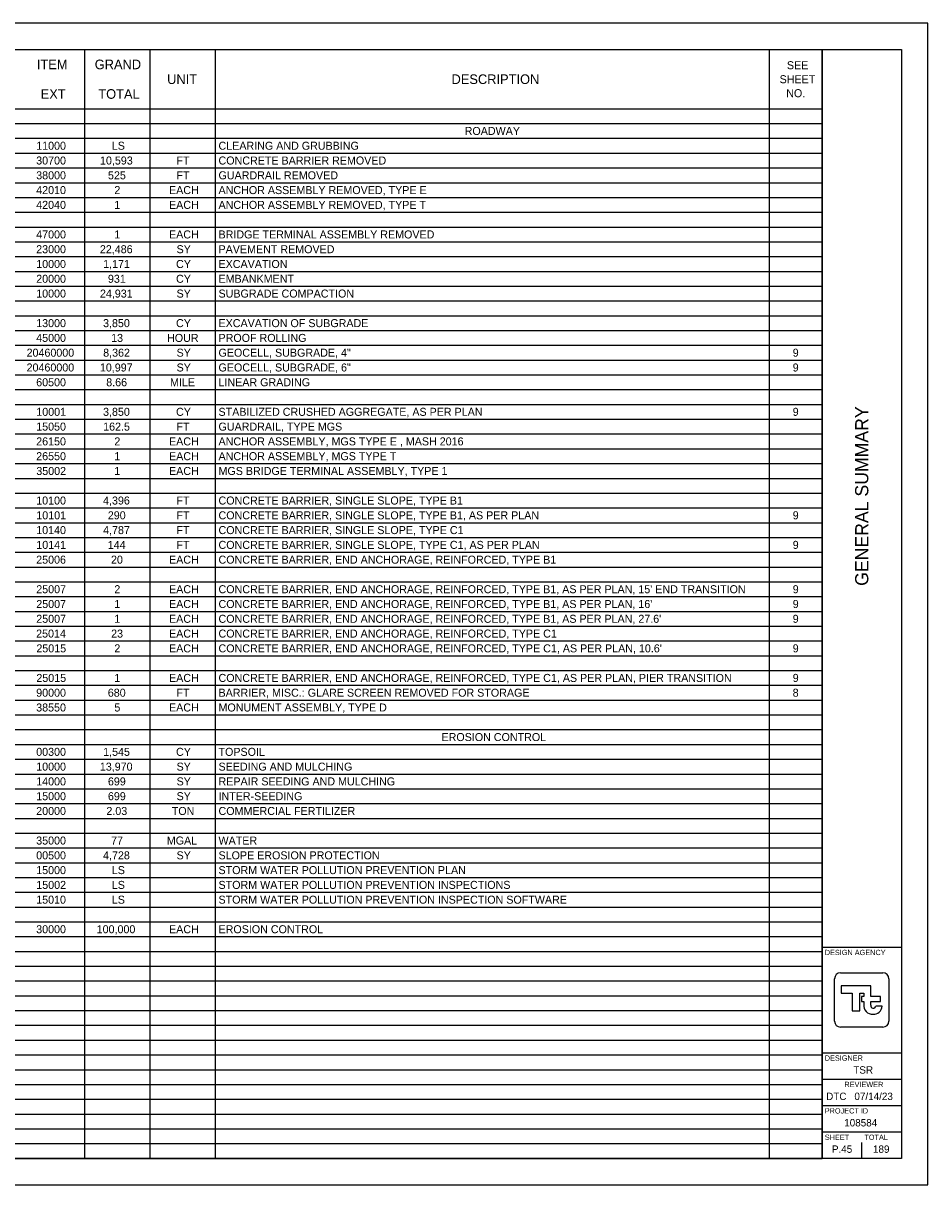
# Model space of a CAD drawing. Extents: x 0 to 34, y 0 to 22.
# Drawn here: x 16.87 to 34, y 0 to 22 of the extents above; entities that cross this region are included whole.
import ezdxf

# ---------------------------------------------------------------- set-up
doc = ezdxf.new("R2010")
doc.units = 0
for name, color, linetype in [('Default', 7, 'Continuous'), ('SH_Border', 7, 'Continuous'), ('SH_Cut_Line', 7, 'Continuous'), ('SH_Data', 7, 'Continuous')]:
    doc.layers.add(name, color=color, linetype=linetype)

msp = doc.modelspace()

# ---------------------------------------------------------------- linework, layer by layer
at = {"layer": 'Default'}
for p, q in [((1.5, 21.5), (32, 21.5)), ((18.035, 21.5), (18.035, 0.5)), ((19.27, 21.5), (19.27, 0.5)), ((20.505, 21.5), (20.505, 0.5)), ((30.995, 21.5), (30.995, 0.5)), ((32, 21.5), (32, 0.5)), ((1.5, 20.38), (32, 20.38)), ((1.5, 20.1), (32, 20.1)), ((1.5, 19.82), (32, 19.82)), ((1.5, 19.54), (32, 19.54)), ((1.5, 19.26), (32, 19.26)), ((1.5, 18.98), (32, 18.98)), ((1.5, 18.7), (32, 18.7)), ((1.5, 18.42), (32, 18.42)), ((1.5, 18.14), (32, 18.14)), ((1.5, 17.86), (32, 17.86)), ((1.5, 17.58), (32, 17.58)), ((1.5, 17.3), (32, 17.3)), ((1.5, 17.02), (32, 17.02)), ((1.5, 16.74), (32, 16.74)), ((1.5, 16.46), (32, 16.46)), ((1.5, 16.18), (32, 16.18)), ((1.5, 15.9), (32, 15.9)), ((1.5, 15.62), (32, 15.62)), ((1.5, 15.34), (32, 15.34)), ((1.5, 15.06), (32, 15.06)), ((1.5, 14.78), (32, 14.78)), ((1.5, 14.5), (32, 14.5)), ((1.5, 14.22), (32, 14.22)), ((1.5, 13.94), (32, 13.94)), ((1.5, 13.66), (32, 13.66)), ((1.5, 13.38), (32, 13.38)), ((1.5, 13.1), (32, 13.1)), ((1.5, 12.82), (32, 12.82)), ((1.5, 12.54), (32, 12.54)), ((1.5, 12.26), (32, 12.26)), ((1.5, 11.98), (32, 11.98)), ((1.5, 11.7), (32, 11.7)), ((1.5, 11.42), (32, 11.42)), ((1.5, 11.14), (32, 11.14)), ((1.5, 10.86), (32, 10.86)), ((1.5, 10.58), (32, 10.58)), ((1.5, 10.3), (32, 10.3)), ((1.5, 10.02), (32, 10.02)), ((1.5, 9.74), (32, 9.74)), ((1.5, 9.46), (32, 9.46)), ((1.5, 9.18), (32, 9.18)), ((1.5, 8.9), (32, 8.9)), ((1.5, 8.62), (32, 8.62)), ((1.5, 8.34), (32, 8.34)), ((1.5, 8.06), (32, 8.06)), ((1.5, 7.78), (32, 7.78)), ((1.5, 7.5), (32, 7.5)), ((1.5, 7.22), (32, 7.22)), ((1.5, 6.94), (32, 6.94)), ((1.5, 6.66), (32, 6.66)), ((1.5, 6.38), (32, 6.38)), ((1.5, 6.1), (32, 6.1)), ((1.5, 5.82), (32, 5.82)), ((1.5, 5.54), (32, 5.54)), ((1.5, 5.26), (32, 5.26)), ((1.5, 4.98), (32, 4.98)), ((1.5, 4.7), (32, 4.7)), ((1.5, 4.42), (32, 4.42)), ((1.5, 4.14), (32, 4.14)), ((1.5, 3.86), (32, 3.86)), ((1.5, 3.58), (32, 3.58)), ((1.5, 3.3), (32, 3.3)), ((1.5, 3.02), (32, 3.02)), ((1.5, 2.74), (32, 2.74)), ((1.5, 2.46), (32, 2.46)), ((1.5, 2.18), (32, 2.18)), ((1.5, 1.9), (32, 1.9)), ((1.5, 1.62), (32, 1.62)), ((1.5, 1.34), (32, 1.34)), ((1.5, 1.06), (32, 1.06)), ((1.5, 0.78), (32, 0.78)), ((1.5, 0.5), (32, 0.5))]:
    msp.add_line(p, q, dxfattribs=at)
at = {"layer": 'SH_Border'}
for p, q in [((32, 0.5), (32, 21.5)), ((32, 4.5), (33.5, 4.5)), ((32, 2.5), (33.5, 2.5)), ((32, 2), (33.5, 2)), ((32, 1.5), (33.5, 1.5)), ((32, 1), (33.5, 1))]:
    msp.add_line(p, q, dxfattribs=at)
msp.add_lwpolyline([(1.5, 21.5), (33.5, 21.5), (33.5, 0.5), (1.5, 0.5)], close=True, dxfattribs=at)
at = {"layer": 'SH_Cut_Line'}
msp.add_lwpolyline([(0, 0), (34, 0), (34, 22), (0, 22)], close=True, dxfattribs=at)
at = {"layer": 'SH_Data'}
for p, q in [((32.75, 3.5), (32.75, 3.5)), ((32.791, 3.415), (32.791, 3.415)), ((33.136, 3.385), (33.015, 3.385)), ((32.375, 0.675), (32.375, 0.675)), ((32.75, 0.5), (32.75, 0.8))]:
    msp.add_line(p, q, dxfattribs=at)
for points in [[(32.348, 4.014), (33.152, 4.014)], [(32.236, 3.099), (32.236, 3.901)], [(32.922, 3.399), (32.922, 3.47), (33.107, 3.47), (33.107, 3.568), (32.922, 3.568), (32.922, 3.768), (32.361, 3.768), (32.361, 3.632), (32.566, 3.632), (32.566, 3.294), (32.715, 3.294), (32.715, 3.63), (32.79, 3.63), (32.79, 3.568), (32.748, 3.568), (32.748, 3.47), (32.79, 3.47), (32.79, 3.415), (32.791, 3.415)], [(33.264, 3.901), (33.264, 3.099)], [(33.152, 2.986), (32.348, 2.986)]]:
    msp.add_lwpolyline(points, dxfattribs=at)
for centre, radius, start, end in [((32.348, 3.901), 0.113, 90, 180), ((33.152, 3.901), 0.113, 360, 90), ((32.949, 3.392), 0.16, 171.8856, 274.8323), ((32.968, 3.392), 0.0473, 171.8856, 350.9243), ((32.976, 3.392), 0.16, 265.1677, 357.3201), ((32.348, 3.099), 0.113, 180, 270), ((33.152, 3.099), 0.113, 270, 360)]:
    msp.add_arc(centre, radius, start, end, dxfattribs=at)

# ---------------------------------------------------------------- texts
at = {"layer": 'Default'}
for s, height, p in [('ITEM', 0.1818, (17.131, 21.129)), ('GRAND', 0.1818, (18.227, 21.129)), ('SEE ', 0.1515, (31.333, 21.129)), ('UNIT', 0.1818, (19.598, 20.849)), ('DESCRIPTION', 0.18184, (24.983, 20.849)), ('SHEET ', 0.1515, (31.195, 20.864)), ('EXT', 0.1818, (17.204, 20.569)), ('TOTAL', 0.1818, (18.295, 20.569)), ('NO.', 0.1515, (31.32, 20.599)), ('ROADWAY', 0.1515, (25.232, 19.884)), ('11000', 0.1515, (17.119, 19.604)), ('LS', 0.1515, (18.551, 19.604)), ('CLEARING AND GRUBBING', 0.15153, (20.571, 19.604)), ('30700', 0.1515, (17.119, 19.324)), ('10,593', 0.1515, (18.327, 19.324)), ('FT', 0.1515, (19.775, 19.324)), ('CONCRETE BARRIER REMOVED', 0.15153, (20.571, 19.324)), ('38000', 0.1515, (17.119, 19.044)), ('525', 0.1515, (18.478, 19.044)), ('FT', 0.1515, (19.775, 19.044)), ('GUARDRAIL REMOVED', 0.15153, (20.571, 19.044)), ('42010', 0.1515, (17.119, 18.764)), ('2', 0.152, (18.598, 18.764)), ('EACH', 0.1515, (19.634, 18.764)), ('ANCHOR ASSEMBLY REMOVED, TYPE E', 0.15153, (20.571, 18.764)), ('42040', 0.1515, (17.119, 18.484)), ('1', 0.152, (18.598, 18.484)), ('EACH', 0.1515, (19.634, 18.484)), ('ANCHOR ASSEMBLY REMOVED, TYPE T', 0.15153, (20.571, 18.484)), ('47000', 0.1515, (17.119, 17.924)), ('1', 0.152, (18.598, 17.924)), ('EACH', 0.1515, (19.634, 17.924)), ('BRIDGE TERMINAL ASSEMBLY REMOVED', 0.15153, (20.571, 17.924)), ('23000', 0.1515, (17.119, 17.644)), ('22,486', 0.1515, (18.325, 17.644)), ('SY', 0.1515, (19.777, 17.644)), ('PAVEMENT REMOVED', 0.15153, (20.571, 17.644)), ('10000', 0.1515, (17.119, 17.364)), ('1,171', 0.1515, (18.387, 17.364)), ('CY', 0.1515, (19.767, 17.364)), ('EXCAVATION', 0.1515, (20.571, 17.364)), ('20000', 0.1515, (17.119, 17.084)), ('931', 0.1515, (18.477, 17.084)), ('CY', 0.1515, (19.767, 17.084)), ('EMBANKMENT', 0.1515, (20.571, 17.084)), ('10000', 0.1515, (17.119, 16.804)), ('24,931', 0.1515, (18.326, 16.804)), ('SY', 0.1515, (19.777, 16.804)), ('SUBGRADE COMPACTION', 0.15153, (20.571, 16.804)), ('13000', 0.1515, (17.119, 16.244)), ('3,850', 0.1515, (18.385, 16.244)), ('CY', 0.1515, (19.767, 16.244)), ('EXCAVATION OF SUBGRADE', 0.15153, (20.571, 16.244)), ('45000', 0.1515, (17.119, 15.964)), ('13', 0.1515, (18.538, 15.964)), ('HOUR', 0.1515, (19.597, 15.964)), ('PROOF ROLLING', 0.15153, (20.571, 15.964)), ('20460000', 0.1515, (16.937, 15.684)), ('8,362', 0.1515, (18.387, 15.684)), ('SY', 0.1515, (19.777, 15.684)), ('GEOCELL, SUBGRADE, 4"', 0.15153, (20.571, 15.684)), ('9', 0.152, (31.443, 15.684)), ('20460000', 0.1515, (16.937, 15.404)), ('10,997', 0.1515, (18.325, 15.404)), ('SY', 0.1515, (19.777, 15.404)), ('GEOCELL, SUBGRADE, 6"', 0.15153, (20.571, 15.404)), ('9', 0.152, (31.443, 15.404)), ('60500', 0.1515, (17.119, 15.124)), ('8.66', 0.1515, (18.445, 15.124)), ('MILE', 0.1515, (19.653, 15.124)), ('LINEAR GRADING', 0.15153, (20.571, 15.124)), ('10001', 0.1515, (17.121, 14.564)), ('3,850', 0.1515, (18.385, 14.564)), ('CY', 0.1515, (19.767, 14.564)), ('STABILIZED CRUSHED AGGREGATE, AS PER PLAN', 0.15153, (20.571, 14.564)), ('9', 0.152, (31.443, 14.564)), ('15050', 0.1515, (17.119, 14.284)), ('162.5', 0.1515, (18.387, 14.284)), ('FT', 0.1515, (19.775, 14.284)), ('GUARDRAIL, TYPE MGS', 0.15153, (20.571, 14.284)), ('26150', 0.1515, (17.119, 14.004)), ('2', 0.152, (18.598, 14.004)), ('EACH', 0.1515, (19.634, 14.004)), ('ANCHOR ASSEMBLY, MGS TYPE E , MASH 2016', 0.15153, (20.571, 14.004)), ('26550', 0.1515, (17.119, 13.724)), ('1', 0.152, (18.598, 13.724)), ('EACH', 0.1515, (19.634, 13.724)), ('ANCHOR ASSEMBLY, MGS TYPE T', 0.15153, (20.571, 13.724)), ('35002', 0.1515, (17.121, 13.444)), ('1', 0.152, (18.598, 13.444)), ('EACH', 0.1515, (19.634, 13.444)), ('MGS BRIDGE TERMINAL ASSEMBLY, TYPE 1', 0.15153, (20.571, 13.444)), ('10100', 0.1515, (17.119, 12.884)), ('4,396', 0.1515, (18.385, 12.884)), ('FT', 0.1515, (19.775, 12.884)), ('CONCRETE BARRIER, SINGLE SLOPE, TYPE B1', 0.15153, (20.571, 12.884)), ('10101', 0.1515, (17.121, 12.604)), ('290', 0.1515, (18.475, 12.604)), ('FT', 0.1515, (19.775, 12.604)), ('CONCRETE BARRIER, SINGLE SLOPE, TYPE B1, AS PER PLAN', 0.15153, (20.571, 12.604)), ('9', 0.152, (31.443, 12.604)), ('10140', 0.1515, (17.119, 12.324)), ('4,787', 0.1515, (18.386, 12.324)), ('FT', 0.1515, (19.775, 12.324)), ('CONCRETE BARRIER, SINGLE SLOPE, TYPE C1', 0.15153, (20.571, 12.324)), ('10141', 0.1515, (17.121, 12.044)), ('144', 0.1515, (18.474, 12.044)), ('FT', 0.1515, (19.775, 12.044)), ('CONCRETE BARRIER, SINGLE SLOPE, TYPE C1, AS PER PLAN', 0.15153, (20.571, 12.044)), ('9', 0.152, (31.443, 12.044)), ('25006', 0.1515, (17.119, 11.764)), ('20', 0.1515, (18.535, 11.764)), ('EACH', 0.1515, (19.634, 11.764)), ('CONCRETE BARRIER, END ANCHORAGE, REINFORCED, TYPE B1', 0.15153, (20.571, 11.764)), ('25007', 0.1515, (17.12, 11.204)), ('2', 0.152, (18.598, 11.204)), ('EACH', 0.1515, (19.634, 11.204)), ("CONCRETE BARRIER, END ANCHORAGE, REINFORCED, TYPE B1, AS PER PLAN, 15' END TRANSITION", 0.15153, (20.571, 11.204)), ('9', 0.152, (31.443, 11.204)), ('25007', 0.1515, (17.12, 10.924)), ('1', 0.152, (18.598, 10.924)), ('EACH', 0.1515, (19.634, 10.924)), ("CONCRETE BARRIER, END ANCHORAGE, REINFORCED, TYPE B1, AS PER PLAN, 16'", 0.15153, (20.571, 10.924)), ('9', 0.152, (31.443, 10.924)), ('25007', 0.1515, (17.12, 10.644)), ('1', 0.152, (18.598, 10.644)), ('EACH', 0.1515, (19.634, 10.644)), ("CONCRETE BARRIER, END ANCHORAGE, REINFORCED, TYPE B1, AS PER PLAN, 27.6'", 0.15153, (20.571, 10.644)), ('9', 0.152, (31.443, 10.644)), ('25014', 0.1515, (17.118, 10.364)), ('23', 0.1515, (18.538, 10.364)), ('EACH', 0.1515, (19.634, 10.364)), ('CONCRETE BARRIER, END ANCHORAGE, REINFORCED, TYPE C1', 0.15153, (20.571, 10.364)), ('25015', 0.1515, (17.122, 10.084)), ('2', 0.152, (18.598, 10.084)), ('EACH', 0.1515, (19.634, 10.084)), ("CONCRETE BARRIER, END ANCHORAGE, REINFORCED, TYPE C1, AS PER PLAN, 10.6'", 0.15153, (20.571, 10.084)), ('9', 0.152, (31.443, 10.084)), ('25015', 0.1515, (17.122, 9.524)), ('1', 0.152, (18.598, 9.524)), ('EACH', 0.1515, (19.634, 9.524)), ('CONCRETE BARRIER, END ANCHORAGE, REINFORCED, TYPE C1, AS PER PLAN, PIER TRANSITION', 0.15153, (20.571, 9.524)), ('9', 0.152, (31.443, 9.524)), ('90000', 0.1515, (17.119, 9.244)), ('680', 0.1515, (18.475, 9.244)), ('FT', 0.1515, (19.775, 9.244)), ('BARRIER, MISC.: GLARE SCREEN REMOVED FOR STORAGE', 0.15153, (20.571, 9.244)), ('8', 0.152, (31.442, 9.244)), ('38550', 0.1515, (17.119, 8.964)), ('5', 0.152, (18.599, 8.964)), ('EACH', 0.1515, (19.634, 8.964)), ('MONUMENT ASSEMBLY, TYPE D', 0.15153, (20.571, 8.964)), ('EROSION CONTROL', 0.15153, (24.793, 8.404)), ('00300', 0.1515, (17.119, 8.124)), ('1,545', 0.1515, (18.387, 8.124)), ('CY', 0.1515, (19.767, 8.124)), ('TOPSOIL', 0.1515, (20.571, 8.124)), ('10000', 0.1515, (17.119, 7.844)), ('13,970', 0.1515, (18.324, 7.844)), ('SY', 0.1515, (19.777, 7.844)), ('SEEDING AND MULCHING', 0.15153, (20.571, 7.844)), ('14000', 0.1515, (17.119, 7.564)), ('699', 0.1515, (18.477, 7.564)), ('SY', 0.1515, (19.777, 7.564)), ('REPAIR SEEDING AND MULCHING', 0.15153, (20.571, 7.564)), ('15000', 0.1515, (17.119, 7.284)), ('699', 0.1515, (18.477, 7.284)), ('SY', 0.1515, (19.777, 7.284)), ('INTER-SEEDING', 0.15153, (20.571, 7.284)), ('20000', 0.1515, (17.119, 7.004)), ('2.03', 0.1515, (18.448, 7.004)), ('TON', 0.1515, (19.686, 7.004)), ('COMMERCIAL FERTILIZER', 0.15153, (20.571, 7.004)), ('35000', 0.1515, (17.119, 6.444)), ('77', 0.1515, (18.537, 6.444)), ('MGAL', 0.1515, (19.592, 6.444)), ('WATER', 0.1515, (20.571, 6.444)), ('00500', 0.1515, (17.119, 6.164)), ('4,728', 0.1515, (18.385, 6.164)), ('SY', 0.1515, (19.777, 6.164)), ('SLOPE EROSION PROTECTION', 0.15153, (20.571, 6.164)), ('15000', 0.1515, (17.119, 5.884)), ('LS', 0.1515, (18.551, 5.884)), ('STORM WATER POLLUTION PREVENTION PLAN', 0.15153, (20.571, 5.884)), ('15002', 0.1515, (17.121, 5.604)), ('LS', 0.1515, (18.551, 5.604)), ('STORM WATER POLLUTION PREVENTION INSPECTIONS', 0.15153, (20.571, 5.604)), ('15010', 0.1515, (17.119, 5.324)), ('LS', 0.1515, (18.551, 5.324)), ('STORM WATER POLLUTION PREVENTION INSPECTION SOFTWARE', 0.15153, (20.571, 5.324)), ('30000', 0.1515, (17.119, 4.764)), ('100,000', 0.1515, (18.264, 4.764)), ('EACH', 0.1515, (19.634, 4.764)), ('EROSION CONTROL', 0.15153, (20.571, 4.764))]:
    msp.add_text(s, height=height, dxfattribs=at).set_placement(p)
at = {"layer": 'SH_Data'}
msp.add_text('GENERAL SUMMARY', height=0.25, rotation=90, dxfattribs=at).set_placement((32.875, 11.344))
for s, height, p in [('DESIGN AGENCY', 0.1, (32.05, 4.35)), ('DESIGNER', 0.1, (32.05, 2.35)), ('TSR', 0.14, (32.59, 2.105)), ('REVIEWER', 0.1, (32.422, 1.85)), ('DTC', 0.14, (32.076, 1.605)), ('07/14/23', 0.14, (32.611, 1.605)), ('PROJECT ID', 0.1, (32.05, 1.35)), ('108584', 0.14, (32.418, 1.105)), ('SHEET', 0.1, (32.05, 0.85)), ('TOTAL', 0.1, (32.8, 0.85)), ('P.45', 0.14, (32.185, 0.605)), ('189', 0.14, (32.963, 0.605))]:
    msp.add_text(s, height=height, dxfattribs=at).set_placement(p)

doc.saveas('drawing.dxf')
